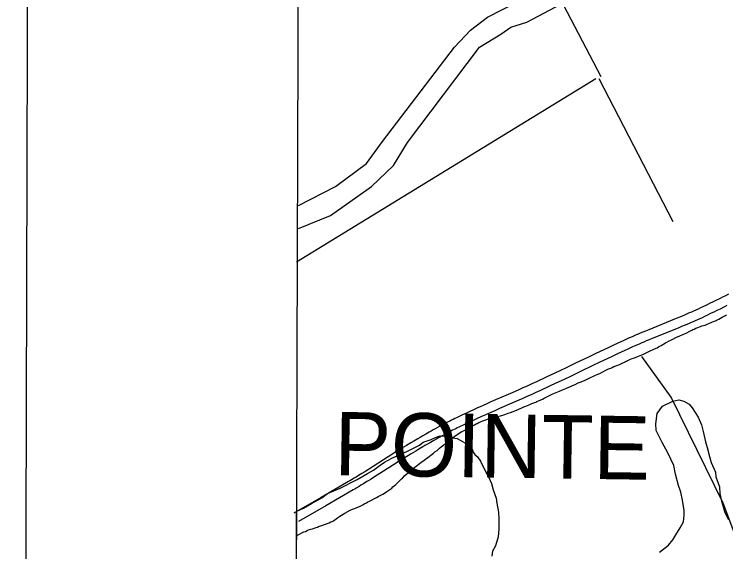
# Model space of a CAD drawing. Extents: x 3161564 to 3199464, y 849354 to 874788.
# Drawn here: x 3164900 to 3167144, y 863951 to 865645 of the extents above; entities that cross this region are included whole.
import ezdxf

# ---------------------------------------------------------------- set-up
doc = ezdxf.new("R2010")
doc.units = 0
for name, color, linetype in [('V-ANNO-SYMB', 7, 'Continuous'), ('V-GRID-FRAM', 7, 'Continuous'), ('V-ROAD-CNTR', 7, 'Continuous'), ('V-SITE-VEGE', 7, 'Continuous'), ('V-TOPO-GNAM-IDEN', 7, 'Continuous'), ('V-TOPO-SHOR', 7, 'Continuous')]:
    doc.layers.add(name, color=color, linetype=linetype)

msp = doc.modelspace()

# ---------------------------------------------------------------- linework, layer by layer
at = {"layer": 'V-ANNO-SYMB'}
msp.add_lwpolyline([(3164899.6, 850655.7), (3197982.7, 850564.3), (3198046, 873480.8), (3164963, 873572.2), (3164899.6, 850655.7)], dxfattribs=at)
at = {"layer": 'V-GRID-FRAM'}
msp.add_lwpolyline([(3165819.2, 873007.6), (3197186.7, 872920.9), (3197144.3, 854733.3), (3165761, 854820), (3165819.2, 873007.6)], dxfattribs=at)
at = {"layer": 'V-ROAD-CNTR'}
for points in [[(3167152.7, 864763.3), (3167142.6, 864758.1), (3167133.8, 864753.7), (3167126, 864749.8), (3167112.5, 864743), (3167102.3, 864738), (3167094.7, 864734.3), (3167083.2, 864728.7), (3167071.7, 864723.2), (3167064, 864719.6), (3167056.6, 864716.1), (3167049.4, 864712.8), (3167042.3, 864709.7), (3167035.5, 864706.7), (3167028.9, 864703.7), (3167022.4, 864701), (3167016.2, 864698.3), (3167004, 864693.1), (3166992.6, 864688.4), (3166981.9, 864683.9), (3166900.8, 864651), (3166890.7, 864646.8), (3166881.8, 864643.1), (3166874, 864639.8), (3166867.2, 864636.9), (3166861.3, 864634.4), (3166850.9, 864629.9), (3166843.1, 864626.5), (3166837.3, 864623.9), (3166828.6, 864620), (3166819.9, 864616), (3166803.2, 864608.3), (3166787.7, 864601), (3166773.1, 864594.1), (3166759.4, 864587.6), (3166733.8, 864575.5), (3166711.4, 864564.8), (3166672.3, 864546.1), (3166642.9, 864532.1), (3166620.9, 864521.6), (3166604.4, 864513.8), (3166579.7, 864502.1), (3166567.3, 864496.3), (3166554.9, 864490.5), (3166547, 864486.8), (3166539.4, 864483.3), (3166532, 864480), (3166517.6, 864473.5), (3166504.1, 864467.4), (3166491.5, 864461.8), (3166479.6, 864456.6), (3166457.2, 864446.8)], [(3167147.3, 864726.9), (3167139.5, 864723), (3167125.8, 864716.2), (3167115.5, 864711.1), (3167107.8, 864707.3), (3167096.2, 864701.7), (3167084.6, 864696.1), (3167076.7, 864692.4), (3167069.1, 864688.9), (3167061.7, 864685.5), (3167054.6, 864682.3), (3167047.6, 864679.2), (3167040.9, 864676.2), (3167034.3, 864673.4), (3167028, 864670.7), (3167015.7, 864665.5), (3167004.1, 864660.6), (3166993.3, 864656.2), (3166912.2, 864623.2), (3166902.1, 864619.1), (3166893.3, 864615.4), (3166885.7, 864612.2), (3166879, 864609.3), (3166873.1, 864606.8), (3166862.9, 864602.4), (3166855.3, 864599.1), (3166849.6, 864596.5), (3166841, 864592.7), (3166832.5, 864588.8), (3166815.9, 864581.1), (3166800.4, 864573.8), (3166785.8, 864567), (3166772.2, 864560.5), (3166746.7, 864548.4), (3166724.3, 864537.7), (3166685.2, 864519), (3166655.8, 864505), (3166633.8, 864494.5), (3166617.3, 864486.7), (3166592.4, 864474.9), (3166580, 864469.1), (3166567.5, 864463.3), (3166559.6, 864459.6), (3166551.9, 864456.1), (3166544.4, 864452.6), (3166529.9, 864446.1), (3166516.3, 864440), (3166503.6, 864434.4), (3166491.6, 864429.1), (3166469.2, 864419.3)], [(3166457.2, 864446.8), (3166418, 864429.7), (3166403.3, 864423.2), (3166390.4, 864417.5), (3166379.1, 864412.5), (3166369.3, 864408.1), (3166360.6, 864404.3), (3166345.6, 864397.5), (3166334.3, 864392.3), (3166325.8, 864388.4), (3166313.2, 864382.5), (3166306.8, 864379.5), (3166300.5, 864376.4), (3166294.7, 864373.7), (3166289.2, 864370.9), (3166283.8, 864368.3), (3166278.6, 864365.7), (3166273.5, 864363.1), (3166268.7, 864360.6), (3166259.3, 864355.8), (3166250.5, 864351.1), (3166242.3, 864346.7), (3166234.7, 864342.6), (3166227.5, 864338.7), (3166220.8, 864335), (3166214.6, 864331.5), (3166208.7, 864328.2), (3166197.8, 864322), (3166188.3, 864316.5), (3166180, 864311.6), (3166172.7, 864307.4), (3166160, 864299.9), (3166150.5, 864294.2), (3166136.4, 864285.7), (3166122.2, 864277.2), (3166116.9, 864274), (3166106.5, 864267.6), (3166096.9, 864261.6), (3166087.9, 864255.9), (3166079.4, 864250.6), (3166016.8, 864210.5), (3166009, 864205.6), (3166002.2, 864201.3), (3165996.2, 864197.5), (3165985.7, 864191), (3165977.8, 864186.2), (3165971.8, 864182.7), (3165962.9, 864177.3), (3165958.4, 864174.7), (3165953.9, 864172.1), (3165867.5, 864122.2), (3165781.1, 864072.3)], [(3166469.2, 864419.3), (3166430, 864402.2), (3166415.3, 864395.7), (3166402.5, 864390.1), (3166391.3, 864385.1), (3166381.5, 864380.8), (3166373, 864376.9), (3166358, 864370.2), (3166346.8, 864365), (3166338.5, 864361.2), (3166326, 864355.3), (3166319.7, 864352.4), (3166313.5, 864349.4), (3166307.9, 864346.7), (3166302.4, 864344), (3166297.1, 864341.4), (3166292.1, 864338.9), (3166287.1, 864336.4), (3166282.4, 864333.9), (3166273.2, 864329.2), (3166264.6, 864324.6), (3166256.5, 864320.3), (3166249, 864316.3), (3166242, 864312.4), (3166235.4, 864308.8), (3166229.3, 864305.3), (3166223.5, 864302.1), (3166212.7, 864295.9), (3166203.3, 864290.5), (3166195.1, 864285.7), (3166187.9, 864281.5), (3166175.3, 864274.1), (3166165.9, 864268.5), (3166151.8, 864260), (3166137.7, 864251.5), (3166132.5, 864248.4), (3166122.3, 864242.1), (3166112.8, 864236.2), (3166103.9, 864230.6), (3166095.6, 864225.3), (3166032.9, 864185.2), (3166025, 864180.2), (3166018.1, 864175.8), (3166012, 864172), (3166001.4, 864165.5), (3165993.3, 864160.6), (3165987.2, 864156.9), (3165978.1, 864151.5), (3165973.5, 864148.8), (3165968.9, 864146.1), (3165882.5, 864096.2), (3165796.1, 864046.3)]]:
    msp.add_lwpolyline(points, dxfattribs=at)
at = {"layer": 'V-SITE-VEGE'}
for p, q in [((3166944.6, 864409.6), (3166977.1, 864426.2)), ((3166977.1, 864426.2), (3166996.2, 864429.8)), ((3166996.2, 864429.8), (3167011.4, 864425.8)), ((3167011.4, 864425.8), (3167028.3, 864416)), ((3167028.3, 864416), (3167037.7, 864404.5)), ((3166927.2, 864387), (3166944.6, 864409.6)), ((3167037.7, 864404.5), (3167056.3, 864375.7)), ((3166922.9, 864354.7), (3166927.2, 864387)), ((3167056.3, 864375.7), (3167067.4, 864350.9)), ((3166924.5, 864333.7), (3166922.9, 864354.7)), ((3167067.4, 864350.9), (3167072.8, 864329.9)), ((3166943, 864295.5), (3166924.5, 864333.7)), ((3167072.8, 864329.9), (3167080, 864297.4)), ((3166189.9, 864296), (3166214.7, 864305.2)), ((3166214.7, 864305.2), (3166228.1, 864310.7)), ((3166228.1, 864310.7), (3166243.4, 864316.2)), ((3166243.4, 864316.2), (3166268.1, 864315.9)), ((3166268.1, 864315.9), (3166283.3, 864310)), ((3166283.3, 864310), (3166296.5, 864307.9)), ((3166296.5, 864307.9), (3166313.5, 864298.2)), ((3166313.5, 864298.2), (3166328.6, 864290.3)), ((3166140.1, 864268.1), (3166178.3, 864286.7)), ((3166178.3, 864286.7), (3166189.9, 864296)), ((3166328.6, 864290.3), (3166343.7, 864274.9)), ((3166961.6, 864262.9), (3166943, 864295.5)), ((3167080, 864297.4), (3167085.5, 864280.2)), ((3167085.5, 864280.2), (3167092.7, 864251.6)), ((3166090.3, 864246), (3166107.5, 864253.4)), ((3166107.5, 864253.4), (3166140.1, 864268.1)), ((3166343.7, 864274.9), (3166347.3, 864265.4)), ((3166347.3, 864265.4), (3166352.9, 864257.7)), ((3166352.9, 864257.7), (3166360.4, 864250)), ((3166980.1, 864222.7), (3166961.6, 864262.9)), ((3166053.9, 864223.6), (3166067.3, 864233)), ((3166067.3, 864233), (3166090.3, 864246)), ((3166360.4, 864250), (3166369.8, 864236.5)), ((3166369.8, 864236.5), (3166373.5, 864228.9)), ((3167092.7, 864251.6), (3167098.2, 864232.5)), ((3167098.2, 864232.5), (3167111.1, 864201.9)), ((3166013.6, 864197.6), (3166032.7, 864208.7)), ((3166032.7, 864208.7), (3166053.9, 864223.6)), ((3166373.5, 864228.9), (3166379.1, 864219.3)), ((3166379.1, 864219.3), (3166388.3, 864200.2)), ((3166985.5, 864196), (3166980.1, 864222.7)), ((3165981, 864179), (3166013.6, 864197.6)), ((3166388.3, 864200.2), (3166395.7, 864186.7)), ((3166395.7, 864186.7), (3166405, 864165.7)), ((3166994.5, 864159.7), (3166985.5, 864196)), ((3167111.1, 864201.9), (3167112.8, 864186.7)), ((3167112.8, 864186.7), (3167123.8, 864156.1)), ((3165927.4, 864151.2), (3165981, 864179)), ((3166405, 864165.7), (3166410.4, 864146.6)), ((3165887.2, 864134.6), (3165927.4, 864151.2)), ((3166410.4, 864146.6), (3166419.6, 864119.9)), ((3167001.8, 864138.7), (3166994.5, 864159.7)), ((3167123.8, 864156.1), (3167125.4, 864135.2)), ((3165837.3, 864102.9), (3165869.9, 864121.5)), ((3165869.9, 864121.5), (3165887.2, 864134.6)), ((3166419.6, 864119.9), (3166421.3, 864104.6)), ((3167007.2, 864113.9), (3167001.8, 864138.7)), ((3167125.4, 864135.2), (3167130.8, 864110.4)), ((3165812.4, 864088), (3165837.3, 864102.9)), ((3166421.3, 864104.6), (3166426.6, 864076)), ((3167012.5, 864081.5), (3167007.2, 864113.9)), ((3167130.8, 864110.4), (3167134.4, 864097)), ((3167134.4, 864097), (3167139.9, 864077.9)), ((3165787, 862926.1), (3165790.7, 864078.5)), ((3165790.7, 864078.5), (3165812.4, 864088)), ((3166426.6, 864076), (3166428.2, 864055.1)), ((3167012.3, 864066.3), (3167012.5, 864081.5)), ((3167139.9, 864077.9), (3167141.7, 864072.2)), ((3166428.2, 864055.1), (3166427.8, 864022.7)), ((3167010.1, 864045.4), (3167012.3, 864066.3)), ((3167141.7, 864072.2), (3167152.8, 864053)), ((3167000.3, 864026.5), (3167010.1, 864045.4)), ((3166427.8, 864022.7), (3166425.5, 863998.1)), ((3166986.7, 864003.9), (3167000.3, 864026.5)), ((3166425.5, 863998.1), (3166417.6, 863969.6)), ((3166963.5, 863971.9), (3166977, 863988.8)), ((3166977, 863988.8), (3166986.7, 864003.9)), ((3166417.6, 863969.6), (3166407.8, 863952.6)), ((3166934.6, 863949.4), (3166963.5, 863971.9)), ((3166407.8, 863952.6), (3166405.7, 863937.5))]:
    msp.add_line(p, q, dxfattribs=at)
at = {"layer": 'V-TOPO-SHOR'}
for p, q in [((3166336, 866242.3), (3166749.7, 865449.6)), ((3165789.6, 864865.3), (3166733.9, 865443.2)), ((3166743.4, 865443.2), (3166977.1, 864991.6))]:
    msp.add_line(p, q, dxfattribs=at)
for points in [[(3165795.9, 865042.2), (3165912.8, 865102.2), (3166010.7, 865174.8), (3166061.2, 865244.3), (3166288.6, 865541.2), (3166339.1, 865594.8), (3166392.8, 865635.9), (3166484.4, 865683.3), (3166595, 865737)], [(3165795.9, 864969.5), (3165897, 865010.6), (3166026.5, 865102.2), (3166096, 865168.5), (3166140.2, 865241.1), (3166367.6, 865541.2), (3166433.9, 865582.2), (3166465.5, 865604.3), (3166516, 865620.1), (3166623.4, 865677)], [(3167049, 864655.6), (3167052.6, 864656.9), (3167064.2, 864661.1), (3167068.5, 864663), (3167073.5, 864664.3), (3167078.6, 864665.8), (3167085.7, 864668.7), (3167090.2, 864670.3), (3167099.8, 864674.3), (3167105.4, 864676.4), (3167108.5, 864678), (3167113.4, 864680.1), (3167117, 864681.7), (3167122.4, 864684.4), (3167132.3, 864690), (3167136.6, 864692.5), (3167142.8, 864695.7), (3167146.2, 864697.5)], [(3166289, 864315.5), (3166293.2, 864318.5), (3166296.4, 864320.4), (3166311.7, 864329.6), (3166316.5, 864332), (3166321.3, 864334.4), (3166327.8, 864338.1), (3166332.4, 864340.3), (3166336.6, 864342.7), (3166351.4, 864351), (3166356.8, 864354), (3166359.6, 864355.6), (3166365.5, 864358.5), (3166372.9, 864361.7), (3166377.4, 864363.9), (3166398.6, 864370.9), (3166404.8, 864373), (3166411.5, 864374.3), (3166417.7, 864376.1), (3166432.9, 864379.6), (3166447, 864383.5), (3166458, 864387.5), (3166465.4, 864390.1), (3166473, 864393), (3166483.7, 864397.5), (3166500.7, 864404.7), (3166507.2, 864407.6), (3166513.4, 864410), (3166523.3, 864414.2), (3166532.3, 864417.9), (3166538.8, 864420.6), (3166544.8, 864422.7), (3166548.2, 864424.3), (3166553.5, 864426.7), (3166565.4, 864432.3), (3166571.1, 864434.9), (3166581.3, 864440), (3166588.1, 864443.8), (3166598, 864448.6), (3166603.7, 864451.3), (3166619.5, 864457.3), (3166629.1, 864461.9), (3166639, 864466.1), (3166644.1, 864468.2), (3166652.3, 864471.1), (3166660.5, 864474.8), (3166668.4, 864478.3), (3166678.6, 864483.1), (3166684.2, 864485.2), (3166693.3, 864489.2), (3166700.6, 864492.4), (3166717, 864500.4), (3166727.2, 864504.6), (3166730.6, 864506.2), (3166740.8, 864510.8), (3166746.2, 864513.4), (3166754.1, 864517.5), (3166765.4, 864523.1), (3166769.7, 864525.2), (3166776.7, 864528.4), (3166781, 864530), (3166785.2, 864531.8), (3166791.2, 864534.5), (3166800.2, 864537.9), (3166803, 864539), (3166808.7, 864541.7), (3166815.5, 864544.9), (3166819.7, 864546.7), (3166822.8, 864548), (3166831, 864551.8), (3166834.1, 864553.4), (3166839.5, 864556.1), (3166842.9, 864557.7), (3166848.9, 864560.3), (3166855.6, 864562.7), (3166868.6, 864568), (3166873.7, 864569.8), (3166883.9, 864574.3), (3166889, 864576.2), (3166901.4, 864582.6), (3166919.3, 864590.3), (3166927.5, 864594.3), (3166932, 864596.7), (3166936.3, 864599.1), (3166940.5, 864601.6), (3166953.8, 864609.1), (3166958.4, 864611.8), (3166965.2, 864615.5), (3166970.9, 864618.5), (3166974.8, 864620.6), (3166988.1, 864627.3), (3166996.6, 864630.5), (3166999.4, 864631.5), (3167008.2, 864635.5), (3167011.3, 864636.9), (3167020.6, 864641.1), (3167028.9, 864645.1), (3167036.5, 864649.4), (3167040.5, 864651.3), (3167043.9, 864653.2), (3167049, 864655.6)], [(3167661, 862811.3), (3167447.8, 863273.1), (3167135.2, 864104.5), (3166971.8, 864438.4), (3166879.4, 864566.3)], [(3165790.4, 864001.3), (3165790.4, 864001.3), (3165797.5, 864005.1), (3165808.9, 864011.3), (3165813.4, 864013.4), (3165818.2, 864015.2), (3165823.6, 864017.6), (3165828.1, 864019.8), (3165835.4, 864021.8), (3165839.9, 864023.1), (3165851.8, 864027.6), (3165855.7, 864028.9), (3165859.4, 864030.2), (3165865.6, 864032.6), (3165870.1, 864034.2), (3165877.8, 864036.8), (3165892.7, 864042.6), (3165898.4, 864045), (3165902.1, 864046.3), (3165904.9, 864047.6), (3165910.6, 864051.7), (3165914.6, 864054.7), (3165920.2, 864058.5), (3165926.5, 864062.8), (3165942.1, 864073.1), (3165959.7, 864082.2), (3165966.2, 864085.1), (3165972.7, 864087.2), (3165977.8, 864089.1), (3165991.1, 864095.2), (3165999, 864098.9), (3166003.5, 864101.6), (3166010.6, 864105.4), (3166015.4, 864108.1), (3166020.5, 864110.5), (3166042.4, 864121.7), (3166047.7, 864124.9), (3166053.4, 864127.9), (3166061.9, 864132.7), (3166067.3, 864136.2), (3166074.7, 864140.8), (3166083.8, 864147.3), (3166090.4, 864151.9), (3166094.1, 864155.2), (3166098.3, 864158.5), (3166103.5, 864163.4), (3166107.2, 864167.2), (3166121.5, 864180.6), (3166124.1, 864183.1), (3166132.1, 864191), (3166138.1, 864196.2), (3166146.4, 864203.5), (3166151.9, 864208.7), (3166154.7, 864211.2), (3166162.7, 864218), (3166171.3, 864224.2), (3166176.4, 864228.3), (3166182.1, 864232.1), (3166192.6, 864240), (3166208.8, 864251.1), (3166214, 864255.4), (3166221.9, 864261.4), (3166226.5, 864265.5), (3166233.1, 864270.4), (3166240.8, 864277.2), (3166246.2, 864282.1), (3166250.8, 864285.4), (3166258.5, 864291.6), (3166260.8, 864293.8), (3166267.9, 864299.5), (3166280.1, 864309), (3166285, 864312.3), (3166289, 864315.5)]]:
    msp.add_lwpolyline(points, dxfattribs=at)

# ---------------------------------------------------------------- texts
at = {"layer": 'V-TOPO-GNAM-IDEN'}
msp.add_text('POINTE', height=200, rotation=359.1825, dxfattribs=at).set_placement((3165908.4, 864192.1))

doc.saveas('drawing.dxf')
